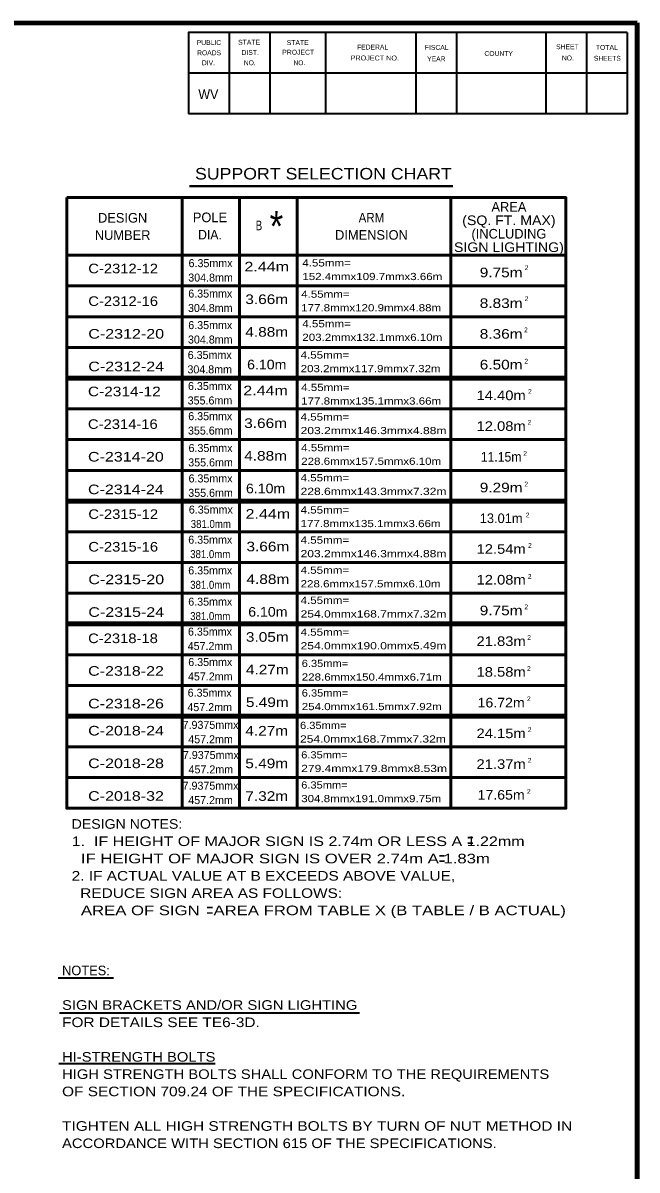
# Model space of a CAD drawing. Extents: x -31 to 824, y -13 to 531.
# Drawn here: x 625.8 to 817.7, y 166.1 to 524.5 of the extents above; entities that cross this region are included whole.
import ezdxf
from ezdxf.enums import TextEntityAlignment as Align

# ---------------------------------------------------------------- set-up
doc = ezdxf.new("R2010")
doc.units = 0
doc.header["$LTSCALE"] = 1.2
doc.layers.add('1', color=7, linetype='Continuous', lineweight=35)
doc.layers.add('61', color=7, linetype='Continuous', lineweight=35)

msp = doc.modelspace()

# ---------------------------------------------------------------- linework, layer by layer
at = {"layer": '1', "lineweight": 158}
msp.add_line((817.693, -1.586), (817.693, 524.514), dxfattribs=at)
at = {"layer": '1', "lineweight": 13}
msp.add_line((817.693, -1.586), (817.693, 524.514), dxfattribs=at)
at = {"layer": '1', "lineweight": 40}
msp.add_line((677.831, 473.559), (760.118, 473.559), dxfattribs=at)
at = {"layer": '1', "lineweight": 53}
for p, q in [((675.473, 279.136), (675.473, 469.936)), ((693.473, 279.136), (693.473, 469.936)), ((711.473, 279.136), (711.473, 469.936)), ((759.473, 279.136), (759.473, 469.936)), ((639.473, 451.936), (795.473, 451.936)), ((639.473, 442.336), (795.473, 442.336)), ((639.473, 432.736), (795.473, 432.736)), ((639.473, 423.136), (795.473, 423.136)), ((639.473, 403.936), (795.473, 403.936)), ((639.473, 394.336), (795.473, 394.336)), ((639.473, 384.736), (795.473, 384.736)), ((639.473, 365.536), (795.473, 365.536)), ((639.473, 355.936), (795.473, 355.936)), ((639.473, 346.336), (795.473, 346.336)), ((639.473, 327.136), (795.473, 327.136)), ((639.473, 317.536), (795.473, 317.536)), ((639.473, 298.336), (795.473, 298.336)), ((639.473, 288.736), (795.473, 288.736))]:
    msp.add_line(p, q, dxfattribs=at)
at = {"layer": '1', "lineweight": 90}
for p, q in [((639.473, 413.536), (795.473, 413.536)), ((639.473, 375.136), (795.473, 375.136)), ((639.473, 336.736), (795.473, 336.736)), ((639.473, 307.936), (795.473, 307.936))]:
    msp.add_line(p, q, dxfattribs=at)
at = {"layer": '1'}
for p, q in [((636.814, 226.146), (654.064, 226.146)), ((637.148, 215.262), (730.942, 215.262)), ((636.981, 199.414), (685.809, 199.414))]:
    msp.add_line(p, q, dxfattribs=at)
at = {"layer": '1', "lineweight": 158}
msp.add_lwpolyline([(817.693, 524.514), (25.993, 524.414), (26.093, -1.586)], dxfattribs=at)
at = {"layer": '1', "lineweight": 53}
msp.add_lwpolyline([(639.473, 469.936), (795.473, 469.936), (795.473, 279.136), (639.473, 279.136)], close=True, dxfattribs=at)
at = {"layer": '61'}
for p, q in [((690.193, 521.514), (690.193, 496.114)), ((702.893, 521.514), (702.893, 496.114)), ((720.293, 521.514), (720.293, 496.114)), ((748.593, 521.514), (748.593, 496.114)), ((761.293, 521.514), (761.293, 496.114)), ((789.193, 521.514), (789.193, 496.114)), ((801.893, 521.514), (801.893, 496.114)), ((814.593, 508.814), (677.493, 508.814))]:
    msp.add_line(p, q, dxfattribs=at)
for points in [[(814.593, 521.514), (677.493, 521.514), (677.493, 496.114)], [(814.593, 521.514), (814.593, 496.114), (677.493, 496.114)]]:
    msp.add_lwpolyline(points, dxfattribs=at)

# ---------------------------------------------------------------- texts
at = {"layer": '1'}
for s, height, width, p in [('WV', 3.048, 0.95, (680.593, 500.714)), ('SUPPORT SELECTION CHART', 3.6, 1.15, (679.533, 475.603)), ('B', 3, 0.75, (698.516, 459.753)), ('*', 9.6, 0.85, (702.846, 456.209)), ('C-2312-12', 3, 1.15, (646.182, 446.292)), ('4.55mm=', 2.25, 1.2, (713.075, 448.422)), ('152.4mmx109.7mmx3.66m', 2.25, 1.2, (713.075, 444.172)), ('4.55mm=', 2.25, 1.2, (712.72, 438.654)), ('C-2312-16', 3, 1.15, (646.182, 436.092)), ('177.8mmx120.9mmx4.88m', 2.25, 1.2, (712.72, 434.404)), ('4.55mm=', 2.25, 1.2, (713.075, 429.419)), ('C-2312-20', 3, 1.25, (646.182, 425.892)), ('203.2mmx132.1mmx6.10m', 2.25, 1.2, (713.075, 425.169)), ('4.55mm=', 2.25, 1.2, (712.543, 419.651)), ('C-2312-24', 3, 1.25, (646.182, 415.692)), ('203.2mmx117.9mmx7.32m', 2.25, 1.2, (712.543, 415.401)), ('C-2314-12', 3, 1.2, (646.082, 407.883)), ('4.55mm=', 2.25, 1.2, (712.72, 409.527)), ('177.8mmx135.1mmx3.66m', 2.25, 1.2, (712.72, 405.277)), ('4.55mm=', 2.25, 1.2, (712.543, 400.292)), ('C-2314-16', 3, 1.15, (646.082, 397.683)), ('203.2mmx146.3mmx4.88m', 2.25, 1.25, (712.543, 396.042)), ('4.55mm=', 2.25, 1.2, (712.72, 390.702)), ('C-2314-20', 3, 1.25, (646.082, 387.483)), ('228.6mmx157.5mmx6.10m', 2.25, 1.2, (712.72, 386.452)), ('4.55mm=', 2.25, 1.2, (712.543, 381.289)), ('C-2314-24', 3, 1.25, (646.082, 377.283)), ('228.6mmx143.3mmx7.32m', 2.25, 1.25, (712.543, 377.039)), ('4.55mm=', 2.25, 1.2, (712.54, 371.243)), ('C-2315-12', 3, 1.15, (646.2, 369.56)), ('177.8mmx135.1mmx3.66m', 2.25, 1.2, (712.54, 366.993)), ('C-2315-16', 3, 1.15, (646.2, 359.36)), ('4.55mm=', 2.25, 1.2, (712.54, 361.831)), ('203.2mmx146.3mmx4.88m', 2.25, 1.25, (712.54, 357.581)), ('C-2315-20', 3, 1.25, (646.2, 349.16)), ('4.55mm=', 2.25, 1.2, (712.54, 352.418)), ('228.6mmx157.5mmx6.10m', 2.25, 1.2, (712.54, 348.168)), ('4.55mm=', 2.25, 1.2, (712.54, 343.005)), ('C-2315-24', 3, 1.25, (646.2, 338.959)), ('254.0mmx168.7mmx7.32m', 2.25, 1.25, (712.54, 338.755)), ('C-2318-18', 3, 1.15, (646.129, 330.755)), ('4.55mm=', 2.25, 1.2, (712.54, 333.059)), ('254.0mmx190.0mmx5.49m', 2.25, 1.25, (712.54, 328.809)), ('C-2318-22', 3, 1.25, (646.129, 320.555)), ('6.35mm=', 2.25, 1.15, (712.895, 323.291)), ('228.6mmx150.4mmx6.71m', 2.25, 1.2, (712.895, 319.041)), ('6.35mm=', 2.25, 1.15, (712.895, 314.056)), ('C-2318-26', 3, 1.25, (646.129, 310.355)), ('254.0mmx161.5mmx7.92m', 2.25, 1.2, (712.895, 309.806)), ('C-2018-24', 3, 1.25, (646.134, 301.894)), ('6.35mm=', 2.25, 1.15, (712.362, 303.933)), ('254.0mmx168.7mmx7.32m', 2.25, 1.25, (712.362, 299.683)), ('C-2018-28', 3, 1.25, (646.134, 291.694)), ('6.35mm=', 2.25, 1.15, (712.726, 294.724)), ('279.4mmx179.8mmx8.53m', 2.25, 1.25, (712.726, 290.474)), ('6.35mm=', 2.25, 1.15, (712.726, 285.311)), ('C-2018-32', 3, 1.25, (646.134, 281.494)), ('304.8mmx191.0mmx9.75m', 2.25, 1.2, (712.726, 281.061)), ('DESIGN NOTES:', 3, 1.1, (640.988, 272.751)), ('1.  IF HEIGHT OF MAJOR SIGN IS 2.74m OR LESS A 1.22mm', 3, 1.25, (640.988, 267.351)), ('=', 4.8, 0.55, (764.539, 266.811)), ('  IF HEIGHT OF MAJOR SIGN IS OVER 2.74m A 1.83m', 3, 1.3, (640.988, 261.951)), ('=', 4.8, 0.55, (755.696, 261.167)), ('2. IF ACTUAL VALUE AT B EXCEEDS ABOVE VALUE,', 3, 1.2, (640.988, 256.551)), ('  REDUCE SIGN AREA AS FOLLOWS:', 3, 1.2, (640.988, 251.151)), ('  AREA OF SIGN   AREA FROM TABLE X (B TABLE / B ACTUAL)', 3, 1.3, (640.988, 245.751)), ('=', 4.8, 0.55, (683.156, 245.005)), ('SIGN BRACKETS AND/OR SIGN LIGHTING', 3, 1.15, (637.983, 216.187)), ('FOR DETAILS SEE TE6-3D.', 3, 1.2, (637.983, 210.787)), ('HI-STRENGTH BOLTS', 3, 1.15, (637.983, 199.987)), ('HIGH STRENGTH BOLTS SHALL CONFORM TO THE REQUIREMENTS', 3, 1.15, (637.983, 194.587)), ('OF SECTION 709.24 OF THE SPECIFICATIONS.', 3, 1.2, (637.983, 189.187)), ('TIGHTEN ALL HIGH STRENGTH BOLTS BY TURN OF NUT METHOD IN', 3, 1.2, (637.983, 178.387)), ('ACCORDANCE WITH SECTION 615 OF THE SPECIFICATIONS.', 3, 1.15, (637.983, 172.987))]:
    msp.add_text(s, height=height, dxfattribs=dict(at, width=width)).set_placement(p)
for s, height, p in [('AREA', 3, (777.64, 465.555)), ('DESIGN', 3, (656.914, 462.135)), ('POLE', 3, (684.211, 462.266)), ('NUMBER', 3, (656.914, 456.735)), ('DIMENSION', 3, (734.681, 456.785)), ('(INCLUDING', 3, (777.64, 457.155)), ('6.35mmx', 2.5, (684.396, 448.213)), ('304.8mm', 2.5, (684.396, 443.713)), ('6.35mmx', 2.5, (684.307, 438.712)), ('304.8mm', 2.5, (684.307, 434.212)), ('6.35mmx', 2.5, (684.307, 428.855)), ('304.8mm', 2.5, (684.307, 424.355)), ('6.35mmx', 2.5, (684.13, 419.531)), ('304.8mm', 2.5, (684.13, 415.031)), ('6.35mmx', 2.5, (684.209, 409.818)), ('355.6mm', 2.5, (684.209, 405.318)), ('6.35mmx', 2.5, (684.298, 400.406)), ('355.6mm', 2.5, (684.298, 395.906)), ('6.35mmx', 2.5, (684.387, 390.46)), ('355.6mm', 2.5, (684.387, 385.96)), ('6.35mmx', 2.5, (684.387, 380.958)), ('355.6mm', 2.5, (684.387, 376.458)), ('6.35mmx', 2.5, (684.477, 371.224)), ('13.01m', 3, (775.212, 368.261)), ('6.35mmx', 2.5, (684.299, 361.812)), ('6.35mmx', 2.5, (684.299, 352.221)), ('6.35mmx', 2.5, (684.299, 342.453)), ('6.35mmx', 2.5, (684.212, 333.092)), ('457.2mm', 2.5, (684.212, 328.592)), ('6.35mmx', 2.5, (684.301, 323.591)), ('457.2mm', 2.5, (684.301, 319.091)), ('6.35mmx', 2.5, (684.123, 314)), ('457.2mm', 2.5, (684.123, 309.5)), ('7.9375mmx', 2.5, (684.389, 303.966)), ('457.2mm', 2.5, (684.389, 299.466)), ('7.9375mmx', 2.5, (684.478, 294.553)), ('457.2mm', 2.5, (684.478, 290.053)), ('7.9375mmx', 2.5, (684.389, 284.963)), ('457.2mm', 2.5, (684.389, 280.463))]:
    msp.add_text(s, height=height, dxfattribs=at).set_placement(p, align=Align.CENTER)
for s, height, width, p in [('ARM', 3, 0.9, (734.681, 462.185)), ('(SQ. FT. MAX)', 3, 1.1, (777.64, 461.355)), ('DIA.', 3, 0.95, (684.211, 456.866)), ('SIGN LIGHTING)', 3, 1.1, (777.64, 452.955)), ('2.44m', 3, 1.25, (701.949, 446.889)), ('9.75m', 3, 1.2, (775.212, 445.061)), ('2', 1.5, 0.9, (783.149, 447.309)), ('3.66m', 3, 1.2, (701.949, 436.689)), ('8.83m', 3, 1.2, (775.212, 435.461)), ('2', 1.5, 0.9, (783.149, 437.63)), ('4.88m', 3, 1.2, (701.949, 426.489)), ('8.36m', 3, 1.2, (775.212, 425.861)), ('2', 1.5, 0.9, (782.971, 427.862)), ('6.10m', 3, 1.1, (701.949, 416.289)), ('2', 1.5, 0.9, (783.06, 418.094)), ('6.50m', 3, 1.2, (775.212, 416.261)), ('2.44m', 3, 1.25, (701.594, 408.172)), ('14.40m', 3, 1.15, (775.212, 406.661)), ('2', 1.5, 0.9, (784.218, 408.642)), ('3.66m', 3, 1.2, (701.594, 397.972)), ('12.08m', 3, 1.15, (775.212, 397.061)), ('2', 1.5, 0.9, (784.04, 398.962)), ('4.88m', 3, 1.2, (701.594, 387.772)), ('2', 1.5, 0.9, (782.709, 389.283)), ('11.15m', 3, 0.95, (775.212, 387.461)), ('6.10m', 3, 1.1, (701.594, 377.572)), ('9.29m', 3, 1.2, (775.211, 377.861)), ('2', 1.5, 0.9, (783.064, 379.693)), ('381.0mm', 2.5, 0.9, (684.477, 366.724)), ('2.44m', 3, 1.25, (702.304, 369.633)), ('2', 1.5, 0.9, (783.508, 370.014)), ('3.66m', 3, 1.2, (702.304, 359.433)), ('2', 1.5, 0.9, (784.218, 360.512)), ('381.0mm', 2.5, 0.9, (684.299, 357.312)), ('12.54m', 3, 1.15, (775.211, 358.661)), ('4.88m', 3, 1.2, (702.304, 349.233)), ('12.08m', 3, 1.15, (775.212, 349.061)), ('2', 1.5, 0.9, (784.129, 350.833)), ('381.0mm', 2.5, 0.9, (684.299, 347.721)), ('381.0mm', 2.5, 0.9, (684.299, 337.953)), ('6.10m', 3, 1.1, (702.304, 339.033)), ('9.75m', 3, 1.2, (775.212, 339.461)), ('2', 1.5, 0.9, (783.064, 341.317)), ('3.05m', 3, 1.2, (702.128, 331.18)), ('21.83m', 3, 1.15, (775.212, 329.861)), ('2', 1.5, 0.9, (783.951, 331.727)), ('4.27m', 3, 1.2, (702.128, 320.98)), ('18.58m', 3, 1.15, (775.212, 320.261)), ('2', 1.5, 0.9, (783.863, 322.047)), ('5.49m', 3, 1.2, (702.128, 310.78)), ('16.72m', 3, 1.1, (775.212, 310.661)), ('2', 1.5, 0.9, (783.863, 312.635)), ('4.27m', 3, 1.2, (701.95, 301.876)), ('24.15m', 3, 1.15, (775.211, 301.061)), ('2', 1.5, 0.9, (784.129, 302.955)), ('5.49m', 3, 1.2, (701.95, 291.676)), ('21.37m', 3, 1.15, (775.212, 291.461)), ('2', 1.5, 0.9, (784.129, 293.365)), ('7.32m', 3, 1.2, (701.95, 281.476)), ('17.65m', 3, 1.1, (775.212, 281.861)), ('2', 1.5, 0.9, (783.863, 283.686))]:
    msp.add_text(s, height=height, dxfattribs=dict(at, width=width)).set_placement(p, align=Align.CENTER)
msp.add_text('NOTES:', height=3, dxfattribs=at).set_placement((637.983, 226.987))
at = {"layer": '61'}
for s, height, rotation, p in [('PUBLIC', 1.525, 0.033, (680.093, 517.614)), ('FEDERAL', 1.523, 0.007, (730.193, 516.214)), ('FISCAL', 1.525, 359.942, (751.393, 516.114)), ('SHEET', 1.525, 0.059, (792.393, 516.314)), ('ROADS', 1.525, 0.124, (680.193, 514.414)), ('DIV.', 1.525, 359.932, (681.693, 511.314)), ('DIST.', 1.525, 0.056, (694.093, 514.514)), ('YEAR', 1.523, 0.105, (752.093, 512.514)), ('COUNTY', 1.523, 0.069, (769.993, 514.214)), ('SHEETS', 1.523, 359.959, (804.193, 512.714))]:
    msp.add_text(s, height=height, rotation=rotation, dxfattribs=at).set_placement(p)
for s, rotation, width, p in [('STATE', 0.059, 1.05, (692.993, 517.714)), ('PROJECT', 359.908, 1.05, (706.793, 514.614)), ('STATE', 0.059, 1.05, (708.193, 517.614)), ('TOTAL', 359.926, 1.05, (804.793, 516.114)), ('NO.', 359.852, 0.9, (694.793, 511.314)), ('NO.', 0.225, 0.9, (710.293, 511.314)), ('PROJECT NO.', 359.922, 1.1, (728.193, 512.814)), ('NO.', 359.852, 0.9, (794.193, 512.814))]:
    msp.add_text(s, height=1.525, rotation=rotation, dxfattribs=dict(at, width=width)).set_placement(p)

doc.saveas('drawing.dxf')
